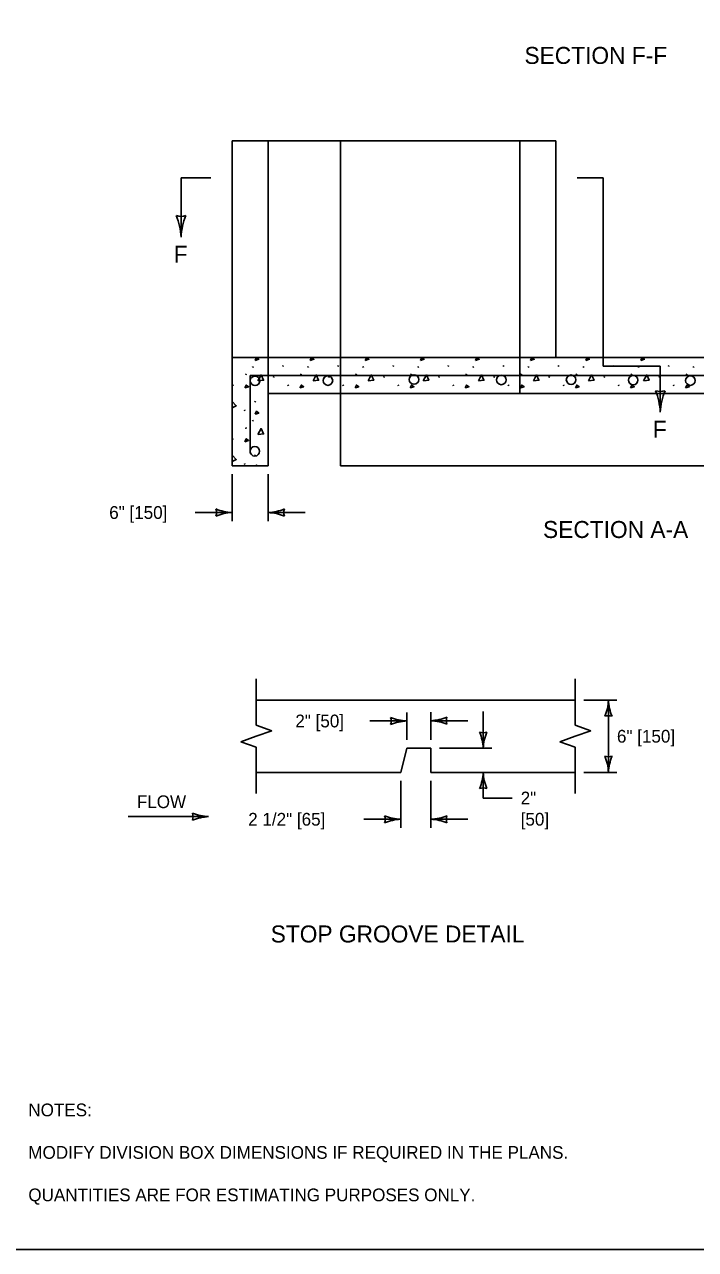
# Model space of a CAD drawing. Extents: x 49991.4 to 50021, y 49987.6 to 50011.4.
# Drawn here: x 50010.91 to 50014.07, y 49987.8 to 49993.57 of the extents above; entities that cross this region are included whole.
import ezdxf

# ---------------------------------------------------------------- set-up
doc = ezdxf.new("R2010")
doc.units = 0
for name, color, linetype in [('Level 1', 7, 'Continuous'), ('Level 2', 7, 'Continuous'), ('Level 3', 7, 'Continuous'), ('Level 4', 7, 'Continuous'), ('Level 6', 7, 'Continuous')]:
    doc.layers.add(name, color=color, linetype=linetype)

msp = doc.modelspace()

# ---------------------------------------------------------------- linework, layer by layer
at = {"layer": 'Level 1'}
for p, q in [((50011.8896, 49991.9984), (50011.8896, 49993.0183)), ((50011.8896, 49993.0183), (50012.2492, 49993.0183)), ((50012.2492, 49993.0183), (50013.4142, 49993.0183)), ((50013.4142, 49991.9984), (50013.4142, 49993.0183)), ((50011.8896, 49991.4884), (50011.8896, 49991.9984)), ((50011.8896, 49991.9984), (50015.6295, 49991.9984)), ((50012.1286, 49991.9558), (50012.1307, 49991.9607)), ((50012.3879, 49991.9558), (50012.39, 49991.9607)), ((50012.6472, 49991.9558), (50012.6493, 49991.9607)), ((50012.9065, 49991.9558), (50012.9086, 49991.9607)), ((50013.1658, 49991.9558), (50013.168, 49991.9607)), ((50013.4251, 49991.9558), (50013.4273, 49991.9607)), ((50013.6844, 49991.9558), (50013.6866, 49991.9607)), ((50013.9437, 49991.9558), (50013.9459, 49991.9607)), ((50011.9537, 49991.9157), (50011.9559, 49991.9205)), ((50011.9746, 49991.5473), (50011.9746, 49991.9134)), ((50011.9746, 49991.9134), (50015.5445, 49991.9134)), ((50011.9856, 49991.9558), (50011.9878, 49991.9526)), ((50011.9878, 49991.9546), (50011.99, 49991.9513)), ((50012.0847, 49991.9032), (50012.0869, 49991.9081)), ((50012.213, 49991.9157), (50012.2152, 49991.9205)), ((50012.2449, 49991.9558), (50012.2471, 49991.9526)), ((50012.2471, 49991.9546), (50012.2493, 49991.9513)), ((50012.344, 49991.9032), (50012.3462, 49991.9081)), ((50012.4723, 49991.9157), (50012.4745, 49991.9205)), ((50012.5043, 49991.9558), (50012.5064, 49991.9526)), ((50012.5064, 49991.9546), (50012.5086, 49991.9513)), ((50012.6033, 49991.9032), (50012.6055, 49991.9081)), ((50012.7316, 49991.9157), (50012.7338, 49991.9205)), ((50012.7636, 49991.9558), (50012.7657, 49991.9526)), ((50012.7657, 49991.9546), (50012.7679, 49991.9513)), ((50012.8626, 49991.9032), (50012.8648, 49991.9081)), ((50012.9909, 49991.9157), (50012.9931, 49991.9205)), ((50013.0229, 49991.9558), (50013.025, 49991.9526)), ((50013.025, 49991.9546), (50013.0272, 49991.9513)), ((50013.1219, 49991.9032), (50013.1241, 49991.9081)), ((50013.2502, 49991.9157), (50013.2524, 49991.9205)), ((50013.2822, 49991.9558), (50013.2843, 49991.9526)), ((50013.2843, 49991.9546), (50013.2865, 49991.9513)), ((50013.3813, 49991.9032), (50013.3834, 49991.9081)), ((50013.5096, 49991.9157), (50013.5117, 49991.9205)), ((50013.5415, 49991.9558), (50013.5437, 49991.9526)), ((50013.5437, 49991.9546), (50013.5458, 49991.9513)), ((50013.6406, 49991.9032), (50013.6427, 49991.9081)), ((50013.7689, 49991.9157), (50013.771, 49991.9205)), ((50013.8008, 49991.9558), (50013.803, 49991.9526)), ((50013.803, 49991.9546), (50013.8051, 49991.9513)), ((50013.8999, 49991.9032), (50013.902, 49991.9081)), ((50014.0282, 49991.9157), (50014.0303, 49991.9205)), ((50014.0601, 49991.9558), (50014.0623, 49991.9526)), ((50014.0623, 49991.9546), (50014.0644, 49991.9513)), ((50011.8931, 49991.8686), (50011.8952, 49991.8653)), ((50012.1524, 49991.8686), (50012.1545, 49991.8653)), ((50012.4117, 49991.8686), (50012.4138, 49991.8653)), ((50012.671, 49991.8686), (50012.6732, 49991.8653)), ((50012.9303, 49991.8686), (50012.9325, 49991.8653)), ((50013.1896, 49991.8686), (50013.1918, 49991.8653)), ((50013.4489, 49991.8686), (50013.4511, 49991.8653)), ((50013.7082, 49991.8686), (50013.7104, 49991.8653)), ((50013.9675, 49991.8686), (50013.9697, 49991.8653)), ((50011.997, 49991.7879), (50011.9992, 49991.7928)), ((50012.0596, 49991.4884), (50012.0596, 49991.8284)), ((50012.0596, 49991.8284), (50015.4595, 49991.8284)), ((50012.3996, 49991.4884), (50012.3996, 49991.8284)), ((50011.9487, 49991.7521), (50011.9492, 49991.7473)), ((50011.9856, 49991.7029), (50011.9878, 49991.6997)), ((50011.9878, 49991.7017), (50011.99, 49991.6984)), ((50011.8931, 49991.6157), (50011.8952, 49991.6125)), ((50011.9537, 49991.6628), (50011.9559, 49991.6677)), ((50011.9487, 49991.4993), (50011.9492, 49991.4944)), ((50011.997, 49991.535), (50011.9992, 49991.5399)), ((50011.8896, 49991.4884), (50012.0596, 49991.4884)), ((50012.3996, 49991.4884), (50015.1195, 49991.4884)), ((50012.0036, 49990.3849), (50013.5052, 49990.3849)), ((50012.6835, 49990.045), (50012.7119, 49990.1583)), ((50012.7119, 49990.1583), (50012.8252, 49990.1583)), ((50012.8252, 49990.1583), (50012.8252, 49990.045)), ((50012.0036, 49990.045), (50012.6835, 49990.045)), ((50012.8252, 49990.045), (50013.5052, 49990.045))]:
    msp.add_line(p, q, dxfattribs=at)
msp.add_lwpolyline([(49999.3835, 49998.9992), (50016.7501, 49998.9992), (50016.7501, 49987.7988), (49999.3835, 49987.7988)], close=True, dxfattribs=at)
for points in [[(50011.9981, 49991.9839), (50012.0046, 49991.9975), (50012.0154, 49991.9894), (50011.9981, 49991.9839)], [(50012.2574, 49991.9839), (50012.2639, 49991.9975), (50012.2747, 49991.9894), (50012.2574, 49991.9839)], [(50012.5167, 49991.9839), (50012.5232, 49991.9975), (50012.534, 49991.9894), (50012.5167, 49991.9839)], [(50012.776, 49991.9839), (50012.7825, 49991.9975), (50012.7933, 49991.9894), (50012.776, 49991.9839)], [(50013.0353, 49991.9839), (50013.0418, 49991.9975), (50013.0527, 49991.9894), (50013.0353, 49991.9839)], [(50013.2946, 49991.9839), (50013.3011, 49991.9975), (50013.312, 49991.9894), (50013.2946, 49991.9839)], [(50013.554, 49991.9839), (50013.5604, 49991.9975), (50013.5713, 49991.9894), (50013.554, 49991.9839)], [(50013.8133, 49991.9839), (50013.8198, 49991.9975), (50013.8306, 49991.9894), (50013.8133, 49991.9839)], [(50012.0116, 49991.8886), (50012.0262, 49991.9162), (50012.0376, 49991.8908), (50012.0122, 49991.8886)], [(50012.2709, 49991.8886), (50012.2855, 49991.9162), (50012.2969, 49991.8908), (50012.2715, 49991.8886)], [(50012.5302, 49991.8886), (50012.5449, 49991.9162), (50012.5562, 49991.8908), (50012.5308, 49991.8886)], [(50012.7896, 49991.8886), (50012.8042, 49991.9162), (50012.8155, 49991.8908), (50012.7901, 49991.8886)], [(50013.0489, 49991.8886), (50013.0635, 49991.9162), (50013.0749, 49991.8908), (50013.0494, 49991.8886)], [(50013.3082, 49991.8886), (50013.3228, 49991.9162), (50013.3342, 49991.8908), (50013.3087, 49991.8886)], [(50013.5675, 49991.8886), (50013.5821, 49991.9162), (50013.5935, 49991.8908), (50013.568, 49991.8886)], [(50013.8268, 49991.8886), (50013.8414, 49991.9162), (50013.8528, 49991.8908), (50013.8273, 49991.8886)], [(50011.9499, 49991.8545), (50011.9564, 49991.868), (50011.9672, 49991.8599), (50011.9499, 49991.8545)], [(50012.2092, 49991.8545), (50012.2157, 49991.868), (50012.2265, 49991.8599), (50012.2092, 49991.8545)], [(50012.4685, 49991.8545), (50012.475, 49991.868), (50012.4858, 49991.8599), (50012.4685, 49991.8545)], [(50012.7278, 49991.8545), (50012.7343, 49991.868), (50012.7452, 49991.8599), (50012.7278, 49991.8545)], [(50012.9871, 49991.8545), (50012.9936, 49991.868), (50013.0045, 49991.8599), (50012.9871, 49991.8545)], [(50013.2465, 49991.8545), (50013.2529, 49991.868), (50013.2638, 49991.8599), (50013.2465, 49991.8545)], [(50013.5058, 49991.8545), (50013.5123, 49991.868), (50013.5231, 49991.8599), (50013.5058, 49991.8545)], [(50013.7651, 49991.8545), (50013.7716, 49991.868), (50013.7824, 49991.8599), (50013.7651, 49991.8545)], [(50014.0244, 49991.8545), (50014.0309, 49991.868), (50014.0417, 49991.8599), (50014.0244, 49991.8545)], [(50011.8896, 49991.7875), (50011.8901, 49991.7911), (50011.9095, 49991.771), (50011.8896, 49991.7618)], [(50012.0747, 49991.8284), (50012.0751, 49991.8293), (50012.0763, 49991.8284)], [(50012.334, 49991.8284), (50012.3344, 49991.8293), (50012.3356, 49991.8284)], [(50012.5933, 49991.8284), (50012.5937, 49991.8293), (50012.5949, 49991.8284)], [(50012.8526, 49991.8284), (50012.853, 49991.8293), (50012.8542, 49991.8284)], [(50013.1119, 49991.8284), (50013.1123, 49991.8293), (50013.1135, 49991.8284)], [(50013.3712, 49991.8284), (50013.3716, 49991.8293), (50013.3728, 49991.8284)], [(50013.6305, 49991.8284), (50013.6309, 49991.8293), (50013.6321, 49991.8284)], [(50013.8898, 49991.8284), (50013.8902, 49991.8293), (50013.8914, 49991.8284)], [(50011.9981, 49991.7311), (50012.0046, 49991.7446), (50012.0154, 49991.7365), (50011.9981, 49991.7311)], [(50011.9499, 49991.6016), (50011.9564, 49991.6152), (50011.9672, 49991.607), (50011.9499, 49991.6016)], [(50012.0116, 49991.6357), (50012.0262, 49991.6633), (50012.0376, 49991.6379), (50012.0122, 49991.6357)], [(50011.8896, 49991.5346), (50011.8901, 49991.5382), (50011.9095, 49991.5182), (50011.8896, 49991.5089)], [(50012.003, 49991.4884), (50012.0046, 49991.4917), (50012.009, 49991.4884)]]:
    msp.add_lwpolyline(points, dxfattribs=at)
for centre in [(50011.9977, 49991.8883), (50012.3407, 49991.8893), (50012.7459, 49991.8942), (50013.1569, 49991.8923), (50013.4853, 49991.8933), (50013.7778, 49991.8914), (50014.0469, 49991.8893), (50011.9968, 49991.5564)]:
    msp.add_circle(centre, 0.0224, dxfattribs=at)
at = {"layer": 'Level 3'}
for p, q in [((50011.8896, 49991.4484), (50011.8896, 49991.2282)), ((50012.0596, 49991.4484), (50012.0596, 49991.2282)), ((50011.8896, 49991.2682), (50011.7162, 49991.2682)), ((50012.0596, 49991.2682), (50012.233, 49991.2682)), ((50013.5452, 49990.3849), (50013.7012, 49990.3849)), ((50013.6612, 49990.045), (50013.6612, 49990.3849)), ((50012.7119, 49990.1983), (50012.7119, 49990.3268)), ((50012.8252, 49990.1983), (50012.8252, 49990.3282)), ((50012.9986, 49990.2882), (50012.8252, 49990.2882)), ((50013.0717, 49990.1583), (50013.0717, 49990.3317)), ((50012.7119, 49990.2868), (50012.5385, 49990.2868)), ((50012.8652, 49990.1583), (50013.1117, 49990.1583)), ((50012.6835, 49990.005), (50012.6835, 49989.7842)), ((50012.8252, 49990.005), (50012.8252, 49989.7842)), ((50013.0717, 49990.045), (50013.0717, 49989.9242)), ((50013.5452, 49990.045), (50013.7012, 49990.045)), ((50013.0717, 49989.9242), (50013.2081, 49989.9242)), ((50011.7793, 49989.8367), (50011.4011, 49989.8367)), ((50012.6835, 49989.8242), (50012.5101, 49989.8242)), ((50012.9986, 49989.8242), (50012.8252, 49989.8242))]:
    msp.add_line(p, q, dxfattribs=at)
for centre, radius, start, end in [((50011.3534, 49992.5523), 0.2964, 2.36048, 22.54399), ((50011.6496, 49992.7354), 0.073, 252.13882, 287.86118), ((50011.9599, 49992.5492), 0.3107, 157.92284, 177.17269), ((50013.905, 49991.9112), 0.073, 252.13882, 287.86118), ((50013.5947, 49991.725), 0.3107, 2.82731, 22.07716), ((50014.2012, 49991.7281), 0.2964, 157.45601, 177.63952), ((50011.8988, 49991.4903), 0.2223, 247.45601, 267.63952), ((50011.7614, 49991.2682), 0.0548, 342.13882, 17.86118), ((50011.9011, 49991.0355), 0.233, 92.82731, 112.07716), ((50012.0481, 49991.5009), 0.233, 272.82731, 292.07716), ((50012.0504, 49991.046), 0.2223, 67.45601, 87.63952), ((50012.1878, 49991.2682), 0.0548, 162.13882, 197.86118), ((50013.439, 49990.394), 0.2223, 337.45601, 357.63952), ((50013.8939, 49990.3964), 0.233, 182.82731, 202.07716), ((50012.721, 49990.5089), 0.2223, 247.45601, 267.63952), ((50012.5837, 49990.2868), 0.0548, 342.13882, 17.86118), ((50012.8137, 49990.5209), 0.233, 272.82731, 292.07716), ((50012.816, 49990.066), 0.2223, 67.45601, 87.63952), ((50012.9534, 49990.2882), 0.0548, 162.13882, 197.86118), ((50013.6612, 49990.2567), 0.0548, 72.13882, 107.86118), ((50012.7234, 49990.0541), 0.233, 92.82731, 112.07716), ((50013.0717, 49990.2865), 0.0548, 252.13882, 287.86118), ((50012.839, 49990.1468), 0.233, 2.82731, 22.07716), ((50013.2938, 49990.1491), 0.2223, 157.45601, 177.63952), ((50013.6612, 49990.1732), 0.0548, 252.13882, 287.86118), ((50013.4285, 49990.0335), 0.233, 2.82731, 22.07716), ((50013.8833, 49990.0358), 0.2223, 157.45601, 177.63952), ((50012.8495, 49990.0541), 0.2223, 337.45601, 357.63952), ((50013.3044, 49990.0565), 0.233, 182.82731, 202.07716), ((50013.0717, 49989.9168), 0.0548, 72.13882, 107.86118), ((50011.7885, 49990.0588), 0.2223, 247.45601, 267.63952), ((50011.6511, 49989.8367), 0.0548, 342.13882, 17.86118), ((50011.7908, 49989.6039), 0.233, 92.82731, 112.07716), ((50012.6926, 49990.0463), 0.2223, 247.45601, 267.63952), ((50012.5553, 49989.8242), 0.0548, 342.13882, 17.86118), ((50012.8137, 49990.0569), 0.233, 272.82731, 292.07716), ((50012.9534, 49989.8242), 0.0548, 162.13882, 197.86118), ((50012.695, 49989.5915), 0.233, 92.82731, 112.07716), ((50012.816, 49989.602), 0.2223, 67.45601, 87.63952)]:
    msp.add_arc(centre, radius, start, end, dxfattribs=at)
at = {"layer": 'Level 4'}
for p, q in [((50012.0596, 49991.8284), (50012.0596, 49993.0183)), ((50012.3996, 49991.8284), (50012.3996, 49993.0183)), ((50013.2442, 49991.8284), (50013.2442, 49993.0183))]:
    msp.add_line(p, q, dxfattribs=at)
at = {"layer": 'Level 6'}
for p, q in [((50011.7896, 49992.8445), (50011.6496, 49992.8445)), ((50011.6496, 49992.5645), (50011.6496, 49992.8445)), ((50013.6366, 49992.8445), (50013.5142, 49992.8445)), ((50013.6366, 49992.8445), (50013.6366, 49991.9579)), ((50013.905, 49991.9579), (50013.6366, 49991.9579)), ((50013.905, 49991.9579), (50013.905, 49991.7403)), ((50012.0036, 49990.4849), (50012.0036, 49990.2668)), ((50013.5052, 49990.4849), (50013.5052, 49990.2668)), ((50012.0767, 49990.2409), (50012.0036, 49990.2668)), ((50012.0767, 49990.2409), (50012.0036, 49990.215)), ((50013.5783, 49990.2409), (50013.5052, 49990.2668)), ((50013.5783, 49990.2409), (50013.5052, 49990.215)), ((50012.0036, 49990.215), (50011.9305, 49990.1891)), ((50012.0036, 49990.1632), (50011.9305, 49990.1891)), ((50013.5052, 49990.215), (50013.4321, 49990.1891)), ((50013.5052, 49990.1632), (50013.4321, 49990.1891)), ((50012.0036, 49990.1632), (50012.0036, 49989.945)), ((50013.5052, 49990.1632), (50013.5052, 49989.945))]:
    msp.add_line(p, q, dxfattribs=at)

# ---------------------------------------------------------------- texts
at = {"layer": 'Level 2'}
for s, height, p in [('SECTION F-F', 0.08, (50013.2659, 49993.38)), ('F', 0.08, (50011.6147, 49992.4445)), ('F', 0.08, (50013.8701, 49991.6203)), ('6" [150]', 0.06, (50011.3112, 49991.2382)), ('SECTION A-A', 0.08, (50013.3533, 49991.1483)), ('2" [50]', 0.06, (50012.1874, 49990.2568)), ('6" [150]', 0.06, (50013.7012, 49990.1849)), ('2"', 0.06, (50013.2481, 49989.8942)), ('FLOW', 0.06, (50011.4414, 49989.8767)), ('2 1/2" [65]', 0.06, (50011.9655, 49989.7942)), ('[50]', 0.06, (50013.2481, 49989.7942)), ('STOP GROOVE DETAIL', 0.08, (50012.0714, 49989.2441)), ('NOTES:', 0.06, (50010.9306, 49988.4258)), ('MODIFY DIVISION BOX DIMENSIONS IF REQUIRED IN THE PLANS.', 0.06, (50010.9306, 49988.2258)), ('QUANTITIES ARE FOR ESTIMATING PURPOSES ONLY.', 0.06, (50010.9306, 49988.0258))]:
    msp.add_text(s, height=height, dxfattribs=at).set_placement(p)

doc.saveas('drawing.dxf')
